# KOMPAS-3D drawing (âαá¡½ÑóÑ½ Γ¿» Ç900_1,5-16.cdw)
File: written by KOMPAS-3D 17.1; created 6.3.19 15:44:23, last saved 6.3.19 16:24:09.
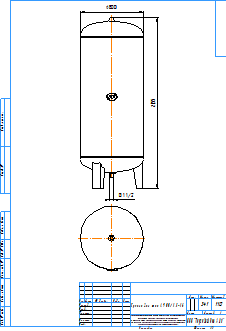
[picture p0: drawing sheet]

Sheet 1: A3, portrait

Title block, sheet 1: name: Гранлевел тип А900/1,5-16; material: Сталь 10  ГОСТ 1050-88; mass: 341; sheets: 1; sheet format: A3; stored path: C:\Users\kka\KOMPAS_Work\!Trash\ГРАНЛЕВЕЛ тип А Расширительный бак\KOMPAS 2D\Гранлевел тип А900_1,5-16.cdw

Views: Вид 1, Проекционный вид 2
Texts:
  kka
  adl
  Рама для чертежей
  Лит-Масса-Масштаб
  Материал-Предприятие
  Масштаб
  Изм.
  Лист
  № докум.
  Подп.
  Дата
  Лит.
  Разраб.
  Пров.
  Т.контр.
  Листов
  Внимание! Данный продукт является объектом авторского права ООО «Торговый Дом АДЛ».
  Запрещается изменение, копирование, распространение
  (в том числе путем копирования на другие сайты и ресурсы в Интернете)
  или любое иное использование информации и объектов без предварительного
  согласия правообладателя (ООО «Торговый Дом АДЛ»).
  Н.контр.
  Утв.
  ООО "Торговый дом АДЛ"
  Изменение
  Номер документа
  Подпись
  Обозначение документа
  Наименование изделия
  Масса изделия по ГОСТ 2.109-73
  Порядковый номер листа
  Общее количество листов в документе
  Характер работы, выполненной лицом, подписавшим документ
  Наименование или индекс предприятия, выпускающего документ
  Инв. № подл.
  Подп. и дата
  Взам. инв. №
  Инв. № дубл.
  Инвентарный номер подлинника по ГОСТ 2.501-68
  Подпись принявшего подлинник в отдел технической документации
  Инвентарный номер подлинника, взамен которого выпущен данный подлинник
  Инвентарный номер дубликата по ГОСТ 2.502-68
  Подпись принявшего дубликат в отдел технической документации
  Справ. №
  Перв. примен.
  Обозначение документа, взамен или на основании которого выпущен данный документ
  Обозначение документа, в котором впервые записан данный документ
  Подпись лица, копировавшего чертеж
  Обозначение формата листа
  !Рама для чертежа
Dimensions and other numbers on the sheet: 2155; 800; 1 1/2; 1:10; 1; 341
